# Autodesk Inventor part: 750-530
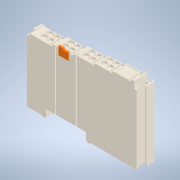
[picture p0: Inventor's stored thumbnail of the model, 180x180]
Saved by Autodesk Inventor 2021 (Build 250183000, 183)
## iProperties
Created: 2026-07
Part Number: 750-530
Material: Generic
Catalog Web Link: www.3dfindit.com
Description: 750-530-8-channel digital output module 24 VDC 0.5 A high-side switching short-circuit protected
Vendor: WAGO
Document SubType Name: Modeling
Designer: psAdmin
Manufacturer: WAGO
Mass: 49.754 g
Surface Area: 192.522 cm^2
Volume: 65.9871 cm^3
Density: 1 g/cm^3
Appearance: PSOLRGB-222-214-201
Category: PARTsolutions
Company: WAGO
Title: 750-530
Author: Cadenas PARTsolutions
Comments: 8-channel digital output module 24 VDC 0.5 A high-side switching short-circuit protected
PSOL_IDENT_0: {$CADENAS_DATA/23d-libs/wago/pg15/serie750/0750-0530_0999-0962.prj},157 {VTYP=3D},{NB=750-530},{LINA=
PSOL_IDENT_1: 750-530},{NN=750-530},{DATE=29.04.2026 11:59:10},{GEOMDATE=22.04.2022 08:42:40},{VERSION=},{LINEID=1
PSOL_IDENT_2: 710},{WBVAR=},{WBNUMERIC=}  {NB=750-530},{LINA=750-530},{KT=DUMMY},{BESTNR=750-530},{INFODE=Info DE}
PSOL_IDENT_3: ,{INFOEN=Info EN},{QUERSCHNITT1=0.08 - 2.5},{QUERSCHNITT2=28 - 14},{ABISOLIERLAENGE=8 - 9},{HOEHE=64
PSOL_IDENT_4: .00},{BREITE=12.00},{TIEFE=100.00},{FARBE=lichtgrau},{GEWICHT=49.754},{BEMERKUNGEN=24V DC 0,5 A},{RG
PSOL_IDENT_5: B=0.87,0.84,0.79,0},{ECLASS71=27-24-26-04},{LINKDE=http://www.wago.com/de/p/750-530},{LINKEN=http://
PSOL_IDENT_6: www.wago.com/global/p/750-530},{FILENAME=750-530}
NB: 750-530
NN: 750-530
NT: 8-channel digital output module 24 VDC 0.5 A high-side switching short-circuit protected
NBSYN: $BESTNR.
LINA: 750-530
CATALOG: WAGO
OFFICIAL_STANDARD_NUMBERS: NO
BESTNR: 750-530
INFODE: Info DE
INFOEN: Info EN
QUERSCHNITT1: 0.08 - 2.5
QUERSCHNITT2: 28 - 14
ABISOLIERLAENGE: 8 - 9
HOEHE: 64
BREITE: 12
TIEFE: 100
FARBE: lichtgrau
GEWICHT: 49.754
BEMERKUNGEN: 24V DC 0,5 A
ECLASS71: 27-24-26-04
SUPPLIER: WAGO
ARTICLENO: 750-530
BOMINFO: 750-530
CREATOR: CADENAS GmbH
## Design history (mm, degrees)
sketch "Skizze_1"
  geometry: L1 (-32.4, 49.707)-(-32.4, -6.4); L2 (-32.4, -6.4)-(-21.968, -6.4); L3 (-21.968, -6.4)-(-20.7, -7.132); L4 (-17.7, -5.4)-(-17.7, 0); L5 (-17.7, 0)-(17.7, 0); L6 (17.7, 0)-(17.7, -5.4); L7 (20.7, -7.132)-(21.968, -6.4); L8 (21.968, -6.4)-(60, -6.4); L9 (60, -6.4)-(60, 59.4); L10 (59, 60.4)-(58.817, 60.4); L11 (58.529, 60.278)-(58.453, 60.199); L12 (59.036, 58.958)-(58.958, 58.766); L13 (58.958, 58.766)-(54.895, 57.042); L14 (54.895, 57.042)-(54.703, 57.119); L15 (54.215, 58.4)-(41.912, 58.4); L16 (41.912, 58.4)-(41.803, 58.354); L17 (41.803, 58.354)-(41.653, 58.199); L18 (42.236, 56.958)-(42.158, 56.766); L19 (42.158, 56.766)-(38.095, 55.042); L20 (38.095, 55.042)-(37.903, 55.119); L21 (37.415, 56.4)-(25.912, 56.4); L22 (25.912, 56.4)-(25.803, 56.354); L23 (25.803, 56.354)-(25.653, 56.199); L24 (26.236, 54.958)-(26.158, 54.766); L25 (26.158, 54.766)-(22.095, 53.042); L26 (22.095, 53.042)-(21.903, 53.119); L27 (21.415, 54.4)-(7.512, 54.4); L28 (7.512, 54.4)-(7.403, 54.354); L29 (7.403, 54.354)-(7.253, 54.199); L30 (7.836, 52.958)-(7.758, 52.766); L31 (7.758, 52.766)-(3.695, 51.042); L32 (3.695, 51.042)-(3.503, 51.119); L33 (3.015, 52.4)-(-10.888, 52.4); L34 (-10.888, 52.4)-(-10.997, 52.354); L35 (-10.997, 52.354)-(-11.147, 52.199); L36 (-10.564, 50.958)-(-10.642, 50.766); L37 (-10.642, 50.766)-(-14.705, 49.042); L38 (-14.705, 49.042)-(-14.897, 49.119); L39 (-15.385, 50.4)-(-32, 50.4); L40 (-32, 50.4)-(-32.4, 49.707); A1 r 2 centre (-19.7, -5.4) between (-20.7, -7.132) and (-17.7, -5.4); A2 r 2 centre (19.7, -5.4) between (17.7, -5.4) and (20.7, -7.132); A3 r 1 centre (59, 59.4) between (60, 59.4) and (59, 60.4); A4 r 0.4 centre (58.817, 60) between (58.817, 60.4) and (58.529, 60.278); A5 r 0.332 centre (58.692, 59.969) between (58.453, 60.199) and (58.644, 59.641); A6 r 0.5 centre (58.572, 59.146) between (59.036, 58.958) and (58.644, 59.641); A7 r 0.5 centre (54.89, 57.583) between (54.484, 57.875) and (54.703, 57.119); A8 r 0.332 centre (54.215, 58.068) between (54.484, 57.875) and (54.215, 58.4); A9 r 0.332 centre (41.892, 57.969) between (41.653, 58.199) and (41.844, 57.641); A10 r 0.5 centre (41.772, 57.146) between (42.236, 56.958) and (41.844, 57.641); A11 r 0.5 centre (38.09, 55.583) between (37.684, 55.875) and (37.903, 55.119); A12 r 0.332 centre (37.415, 56.068) between (37.684, 55.875) and (37.415, 56.4); A13 r 0.332 centre (25.892, 55.969) between (25.653, 56.199) and (25.844, 55.641); A14 r 0.5 centre (25.772, 55.146) between (26.236, 54.958) and (25.844, 55.641); A15 r 0.5 centre (22.09, 53.583) between (21.684, 53.875) and (21.903, 53.119); A16 r 0.332 centre (21.415, 54.068) between (21.684, 53.875) and (21.415, 54.4); A17 r 0.331 centre (7.492, 53.969) between (7.253, 54.199) and (7.444, 53.641); A18 r 0.5 centre (7.372, 53.146) between (7.836, 52.958) and (7.444, 53.641); A19 r 0.5 centre (3.69, 51.583) between (3.284, 51.875) and (3.503, 51.119); A20 r 0.332 centre (3.015, 52.068) between (3.284, 51.875) and (3.015, 52.4); A21 r 0.332 centre (-10.908, 51.969) between (-11.147, 52.199) and (-10.956, 51.641); A22 r 0.5 centre (-11.028, 51.146) between (-10.564, 50.958) and (-10.956, 51.641); A23 r 0.5 centre (-14.71, 49.583) between (-15.116, 49.875) and (-14.897, 49.119); A24 r 0.332 centre (-15.385, 50.068) between (-15.116, 49.875) and (-15.385, 50.4)
  constraints: 80 end point, 48 point on circle, 24 centre point
extrude "Extrusion1" join sketch "Skizze_1" distance "d0" = 12; taper "d1" = 0 deg
sketch "Skizze_10"
  geometry: L1 (37.2, 56.4)-(37.981, 54.559); L2 (37.981, 54.559)-(42.693, 56.559); L3 (42.693, 56.559)-(41.912, 58.4); L4 (41.912, 58.4)-(41.342, 58.158); L5 (40.812, 56.847)-(38.971, 56.066); L6 (37.66, 56.595)-(37.2, 56.4); A1 r 1 centre (41.733, 57.238) between (41.342, 58.158) and (40.812, 56.847); A2 r 1 centre (38.051, 55.675) between (38.971, 56.066) and (37.66, 56.595)
  constraints: 12 end point, 4 point on circle, 2 centre point
extrude "Extrusion2" join sketch "Skizze_10" distance "d2" = 0.5; taper "d3" = 0 deg
sketch "Skizze_11"
  geometry: L1 (21.2, 54.4)-(21.981, 52.559); L2 (21.981, 52.559)-(26.693, 54.559); L3 (26.693, 54.559)-(25.912, 56.4); L4 (25.912, 56.4)-(25.342, 56.158); L5 (24.812, 54.847)-(22.971, 54.066); L6 (21.66, 54.595)-(21.2, 54.4); A1 r 1 centre (25.733, 55.238) between (25.342, 56.158) and (24.812, 54.847); A2 r 1 centre (22.051, 53.675) between (22.971, 54.066) and (21.66, 54.595)
  constraints: 12 end point, 4 point on circle, 2 centre point
extrude "Extrusion3" join sketch "Skizze_11" distance "d4" = 0.5; taper "d5" = 0 deg
sketch "Skizze_12"
  geometry: L1 (2.8, 52.4)-(3.581, 50.559); L2 (3.581, 50.559)-(8.293, 52.559); L3 (8.293, 52.559)-(7.512, 54.4); L4 (7.512, 54.4)-(6.942, 54.158); L5 (6.412, 52.847)-(4.571, 52.066); L6 (3.26, 52.595)-(2.8, 52.4); A1 r 1 centre (7.333, 53.238) between (6.942, 54.158) and (6.412, 52.847); A2 r 1 centre (3.651, 51.675) between (4.571, 52.066) and (3.26, 52.595)
  constraints: 12 end point, 4 point on circle, 2 centre point
extrude "Extrusion4" join sketch "Skizze_12" distance "d6" = 0.5; taper "d7" = 0 deg
sketch "Skizze_13"
  geometry: L1 (-15.6, 50.4)-(-14.819, 48.559); L2 (-14.819, 48.559)-(-10.107, 50.559); L3 (-10.107, 50.559)-(-10.888, 52.4); L4 (-10.888, 52.4)-(-11.458, 52.158); L5 (-11.988, 50.847)-(-13.829, 50.066); L6 (-15.14, 50.595)-(-15.6, 50.4); A1 r 1 centre (-11.067, 51.238) between (-11.458, 52.158) and (-11.988, 50.847); A2 r 1 centre (-14.749, 49.675) between (-13.829, 50.066) and (-15.14, 50.595)
  constraints: 12 end point, 4 point on circle, 2 centre point
extrude "Extrusion5" join sketch "Skizze_13" distance "d8" = 0.5; taper "d9" = 0 deg
sketch "Skizze_60"
  geometry: L1 (54, 58.4)-(54.781, 56.559); L2 (54.781, 56.559)-(59.493, 58.559); L3 (59.493, 58.559)-(58.712, 60.4); L4 (58.712, 60.4)-(58.142, 60.158); L5 (57.612, 58.847)-(55.771, 58.066); L6 (54.46, 58.595)-(54, 58.4); A1 r 1 centre (58.533, 59.238) between (58.142, 60.158) and (57.612, 58.847); A2 r 1 centre (54.851, 57.675) between (55.771, 58.066) and (54.46, 58.595)
  constraints: 12 end point, 4 point on circle, 2 centre point
extrude "Extrusion6" join sketch "Skizze_60" distance "d10" = 0.5; taper "d11" = 0 deg
sketch "Skizze_14"
  geometry: L1 (37.2, 56.4)-(37.981, 54.559); L2 (37.981, 54.559)-(42.693, 56.559); L3 (42.693, 56.559)-(41.912, 58.4); L4 (41.912, 58.4)-(41.342, 58.158); L5 (40.812, 56.847)-(38.971, 56.066); L6 (37.66, 56.595)-(37.2, 56.4); A1 r 1 centre (41.733, 57.238) between (41.342, 58.158) and (40.812, 56.847); A2 r 1 centre (38.051, 55.675) between (38.971, 56.066) and (37.66, 56.595)
  constraints: 12 end point, 4 point on circle, 2 centre point
extrude "Extrusion7" join sketch "Skizze_14" distance "d12" = 0.5; taper "d13" = 0 deg
sketch "Skizze_15"
  geometry: L1 (21.2, 54.4)-(21.981, 52.559); L2 (21.981, 52.559)-(26.693, 54.559); L3 (26.693, 54.559)-(25.912, 56.4); L4 (25.912, 56.4)-(25.342, 56.158); L5 (24.812, 54.847)-(22.971, 54.066); L6 (21.66, 54.595)-(21.2, 54.4); A1 r 1 centre (25.733, 55.238) between (25.342, 56.158) and (24.812, 54.847); A2 r 1 centre (22.051, 53.675) between (22.971, 54.066) and (21.66, 54.595)
  constraints: 12 end point, 4 point on circle, 2 centre point
extrude "Extrusion8" join sketch "Skizze_15" distance "d14" = 0.5; taper "d15" = 0 deg
sketch "Skizze_16"
  geometry: L1 (2.8, 52.4)-(3.581, 50.559); L2 (3.581, 50.559)-(8.293, 52.559); L3 (8.293, 52.559)-(7.512, 54.4); L4 (7.512, 54.4)-(6.942, 54.158); L5 (6.412, 52.847)-(4.571, 52.066); L6 (3.26, 52.595)-(2.8, 52.4); A1 r 1 centre (7.333, 53.238) between (6.942, 54.158) and (6.412, 52.847); A2 r 1 centre (3.651, 51.675) between (4.571, 52.066) and (3.26, 52.595)
  constraints: 12 end point, 4 point on circle, 2 centre point
extrude "Extrusion9" join sketch "Skizze_16" distance "d16" = 0.5; taper "d17" = 0 deg
sketch "Skizze_17"
  geometry: L1 (-15.6, 50.4)-(-14.819, 48.559); L2 (-14.819, 48.559)-(-10.107, 50.559); L3 (-10.107, 50.559)-(-10.888, 52.4); L4 (-10.888, 52.4)-(-11.458, 52.158); L5 (-11.988, 50.847)-(-13.829, 50.066); L6 (-15.14, 50.595)-(-15.6, 50.4); A1 r 1 centre (-11.067, 51.238) between (-11.458, 52.158) and (-11.988, 50.847); A2 r 1 centre (-14.749, 49.675) between (-13.829, 50.066) and (-15.14, 50.595)
  constraints: 12 end point, 4 point on circle, 2 centre point
extrude "Extrusion10" join sketch "Skizze_17" distance "d18" = 0.5; taper "d19" = 0 deg
sketch "Skizze_61"
  geometry: L1 (54, 58.4)-(54.781, 56.559); L2 (54.781, 56.559)-(59.493, 58.559); L3 (59.493, 58.559)-(58.712, 60.4); L4 (58.712, 60.4)-(58.142, 60.158); L5 (57.612, 58.847)-(55.771, 58.066); L6 (54.46, 58.595)-(54, 58.4); A1 r 1 centre (58.533, 59.238) between (58.142, 60.158) and (57.612, 58.847); A2 r 1 centre (54.851, 57.675) between (55.771, 58.066) and (54.46, 58.595)
  constraints: 12 end point, 4 point on circle, 2 centre point
extrude "Extrusion11" join sketch "Skizze_61" distance "d20" = 0.5; taper "d21" = 0 deg
sketch "Skizze_46"
  geometry: L1 (-7.3, 46.4)-(2.5, 46.4); L2 (2.5, 46.4)-(2.5, 52.4); L3 (2.5, 52.4)-(-7.3, 52.4); L4 (-7.3, 52.4)-(-7.3, 46.4)
  constraints: 8 end point
extrude "Extrusion12" cut sketch "Skizze_46" distance "d22" = 1.9; taper "d23" = 0 deg
sketch "Skizze_47"
  geometry: L1 (-7, 53.4)-(-7, 46.6); L2 (-6.8, 46.4)-(2, 46.4); L3 (2.2, 46.6)-(2.2, 52.2); L4 (2, 52.4)-(-3.3, 52.4); L5 (-3.331, 52.998)-(-2.325, 53.101); L6 (-2.35, 53.6)-(-6.8, 53.6); A1 r 0.2 centre (-6.8, 46.6) between (-7, 46.6) and (-6.8, 46.4); A2 r 0.2 centre (2, 46.6) between (2, 46.4) and (2.2, 46.6); A3 r 0.2 centre (2, 52.2) between (2.2, 52.2) and (2, 52.4); A4 r 0.3 centre (-3.3, 52.7) between (-3.331, 52.998) and (-3.3, 52.4); A5 r 0.25 centre (-2.35, 53.35) between (-2.325, 53.101) and (-2.35, 53.6); A6 r 0.2 centre (-6.8, 53.4) between (-6.8, 53.6) and (-7, 53.4)
  constraints: 12 end point, 12 point on circle, 6 centre point
extrude "Extrusion13" join sketch "Skizze_47" stored distance "d24" = 1.6; taper "d25" = 0 deg
sketch "Skizze_2"
  geometry: L1 (60, 0)-(60, -1.7); L2 (60.5, -1.2)-(61.9, -1.2); L3 (62.4, -1.7)-(62.4, -4.3); L4 (63.8, -4.3)-(63.8, 1.8); L5 (62.8, 2.8)-(61.3, 2.8); L6 (60.8, 2.3)-(60.8, 1.9); L7 (61, 1.7)-(62.2, 1.7); L8 (62.4, 1.5)-(62.4, 0.2); L9 (62.2, 0)-(60, 0); A1 r 0.5 centre (60.5, -1.7) between (60.5, -1.2) and (60, -1.7); A2 r 0.5 centre (61.9, -1.7) between (62.4, -1.7) and (61.9, -1.2); A3 r 0.7 centre (63.1, -4.3) between (62.4, -4.3) and (63.8, -4.3); A4 r 1 centre (62.8, 1.8) between (63.8, 1.8) and (62.8, 2.8); A5 r 0.5 centre (61.3, 2.3) between (61.3, 2.8) and (60.8, 2.3); A6 r 0.2 centre (61, 1.9) between (60.8, 1.9) and (61, 1.7); A7 r 0.2 centre (62.2, 1.5) between (62.4, 1.5) and (62.2, 1.7); A8 r 0.2 centre (62.2, 0.2) between (62.2, 0) and (62.4, 0.2)
  constraints: 18 end point, 16 point on circle, 8 centre point
extrude "Extrusion14" join sketch "Skizze_2" distance "d26" = 60.8; taper "d27" = 0 deg
sketch "Skizze_3"
  geometry: L1 (-34.8, -4.3)-(-34.8, -1.7); L2 (-34.3, -1.2)-(-32.9, -1.2); L3 (-32.4, -1.7)-(-32.4, 0); L4 (-32.4, 0)-(-34.6, 0); L5 (-34.8, 0.2)-(-34.8, 1.5); L6 (-34.6, 1.7)-(-33.4, 1.7); L7 (-33.2, 1.9)-(-33.2, 2.3); L8 (-33.7, 2.8)-(-35.2, 2.8); L9 (-36.2, 1.8)-(-36.2, -4.3); A1 r 0.7 centre (-35.5, -4.3) between (-36.2, -4.3) and (-34.8, -4.3); A2 r 0.5 centre (-34.3, -1.7) between (-34.3, -1.2) and (-34.8, -1.7); A3 r 0.5 centre (-32.9, -1.7) between (-32.4, -1.7) and (-32.9, -1.2); A4 r 0.2 centre (-34.6, 0.2) between (-34.8, 0.2) and (-34.6, 0); A5 r 0.2 centre (-34.6, 1.5) between (-34.6, 1.7) and (-34.8, 1.5); A6 r 0.2 centre (-33.4, 1.9) between (-33.4, 1.7) and (-33.2, 1.9); A7 r 0.5 centre (-33.7, 2.3) between (-33.2, 2.3) and (-33.7, 2.8); A8 r 1 centre (-35.2, 1.8) between (-35.2, 2.8) and (-36.2, 1.8)
  constraints: 18 end point, 16 point on circle, 8 centre point
extrude "Extrusion15" join sketch "Skizze_3" distance "d28" = 54.8; taper "d29" = 0 deg
sketch "Skizze_9"
  geometry: L1 (-34.6, -10.6)-(-34.6, -11.8); L2 (-34.4, -12)-(-32.4, -12); L3 (-32.4, -12)-(-32.4, -7); L4 (-32.4, -7)-(-33, -7); L5 (-33, -7)-(-33, -10.4); L6 (-33, -10.4)-(-34.4, -10.4); A1 r 0.2 centre (-34.4, -11.8) between (-34.6, -11.8) and (-34.4, -12); A2 r 0.2 centre (-34.4, -10.6) between (-34.4, -10.4) and (-34.6, -10.6)
  constraints: 12 end point, 4 point on circle, 2 centre point
extrude "Extrusion16" join sketch "Skizze_9" distance "d30" = 54.8; taper "d31" = 0 deg
sketch "Skizze_8"
  geometry: L1 (60, -7)-(60, -12); L2 (60, -12)-(62, -12); L3 (62.2, -11.8)-(62.2, -10.6); L4 (62, -10.4)-(60.6, -10.4); L5 (60.6, -10.4)-(60.6, -7); L6 (60.6, -7)-(60, -7); A1 r 0.2 centre (62, -11.8) between (62, -12) and (62.2, -11.8); A2 r 0.2 centre (62, -10.6) between (62.2, -10.6) and (62, -10.4)
  constraints: 12 end point, 4 point on circle, 2 centre point
extrude "Extrusion17" join sketch "Skizze_8" distance "d32" = 60.8; taper "d33" = 0 deg
sketch "Sketch18"
  geometry: 1 further point
hole "Hole1" sketch "Sketch18" at (3.188, 9.5) diameter "d34" = 4.2; stored, may be unused: countersink angle "d38" = 90 deg, drill point angle "d40" = 0 deg; dims "d35" = 6, "d36" = 5.4, "d37" = 2, "d39" = 2
pattern_linear "Rectangular Pattern1" dims "d43" = 5, "d46" = 0
sketch "Skizze_24"
  geometry: L1 (-2.5, 54.4)-(-2.5, 56.4); L2 (-2.5, 56.4)-(-1.2, 56.4); L3 (-1.2, 56.4)-(-1.4, 55.8); L4 (-1.4, 55.8)-(-1.4, 54.4); L5 (-1.4, 54.4)-(-2.5, 54.4); L6 (-2.5, 54.4)-(-2.5, 56.4)
  constraints: 12 end point
revolve "Revolution1" sketch "Skizze_24" stored, may be unused: angle "d47" = 360 deg
pattern_linear "Rectangular Pattern2" dims "d50" = 5, "d53" = 0
sketch "Skizze_26"
  geometry: L1 (-4.5, 54.4)-(-0.8, 54.4); L2 (-0.8, 54.4)-(-0.8, 56.4); L3 (-0.8, 56.4)-(-4.5, 56.4); L4 (-4.5, 56.4)-(-4.5, 54.4)
  constraints: 8 end point
extrude "Extrusion18" cut sketch "Skizze_26" distance "d54" = 3.8; taper "d55" = 0 deg
pattern_linear "Rectangular Pattern3" dims "d58" = 5, "d61" = 0
sketch "Sketch21"
  geometry: 1 further point
hole "Hole2" sketch "Sketch21" at (5.588, 9.5) diameter "d62" = 4.2; stored, may be unused: countersink angle "d66" = 90 deg, drill point angle "d68" = 0 deg; dims "d63" = 6, "d64" = 5.4, "d65" = 2, "d67" = 2
pattern_linear "Rectangular Pattern4" dims "d71" = 5, "d74" = 0
sketch "Skizze_30"
  geometry: L1 (-2.5, 52.4)-(-2.5, 54.4); L2 (-2.5, 54.4)-(-1.2, 54.4); L3 (-1.2, 54.4)-(-1.4, 53.8); L4 (-1.4, 53.8)-(-1.4, 52.4); L5 (-1.4, 52.4)-(-2.5, 52.4); L6 (-2.5, 52.4)-(-2.5, 54.4)
  constraints: 12 end point
revolve "Revolution2" sketch "Skizze_30" stored, may be unused: angle "d75" = 360 deg
pattern_linear "Rectangular Pattern5" dims "d78" = 5, "d81" = 0
sketch "Skizze_32"
  geometry: L1 (-4.5, 52.4)-(-0.8, 52.4); L2 (-0.8, 52.4)-(-0.8, 54.4); L3 (-0.8, 54.4)-(-4.5, 54.4); L4 (-4.5, 54.4)-(-4.5, 52.4)
  constraints: 8 end point
extrude "Extrusion19" cut sketch "Skizze_32" distance "d82" = 3.8; taper "d83" = 0 deg
pattern_linear "Rectangular Pattern6" dims "d86" = 5, "d89" = 0
sketch "Sketch24"
  geometry: 1 further point
hole "Hole3" sketch "Sketch24" at (5.588, 9.5) diameter "d90" = 4.2; stored, may be unused: countersink angle "d94" = 90 deg, drill point angle "d96" = 0 deg; dims "d91" = 6, "d92" = 5.4, "d93" = 2, "d95" = 2
pattern_linear "Rectangular Pattern7" dims "d99" = 5, "d102" = 0
sketch "Skizze_36"
  geometry: L1 (-2.5, 50.4)-(-2.5, 52.4); L2 (-2.5, 52.4)-(-1.2, 52.4); L3 (-1.2, 52.4)-(-1.4, 51.8); L4 (-1.4, 51.8)-(-1.4, 50.4); L5 (-1.4, 50.4)-(-2.5, 50.4); L6 (-2.5, 50.4)-(-2.5, 52.4)
  constraints: 12 end point
revolve "Revolution3" sketch "Skizze_36" stored, may be unused: angle "d103" = 360 deg
pattern_linear "Rectangular Pattern8" dims "d106" = 5, "d109" = 0
sketch "Skizze_38"
  geometry: L1 (-4.5, 50.4)-(-0.8, 50.4); L2 (-0.8, 50.4)-(-0.8, 52.4); L3 (-0.8, 52.4)-(-4.5, 52.4); L4 (-4.5, 52.4)-(-4.5, 50.4)
  constraints: 8 end point
extrude "Extrusion20" cut sketch "Skizze_38" distance "d110" = 3.8; taper "d111" = 0 deg
pattern_linear "Rectangular Pattern9" dims "d114" = 5, "d117" = 0
sketch "Sketch27"
  geometry: 1 further point
hole "Hole4" sketch "Sketch27" at (8.3, 9.5) diameter "d118" = 4.2; stored, may be unused: countersink angle "d122" = 90 deg, drill point angle "d124" = 0 deg; dims "d119" = 6, "d120" = 5.4, "d121" = 2, "d123" = 2
pattern_linear "Rectangular Pattern10" dims "d127" = 5, "d130" = 0
sketch "Skizze_42"
  geometry: L1 (-2.5, 48.4)-(-2.5, 50.4); L2 (-2.5, 50.4)-(-1.2, 50.4); L3 (-1.2, 50.4)-(-1.4, 49.8); L4 (-1.4, 49.8)-(-1.4, 48.4); L5 (-1.4, 48.4)-(-2.5, 48.4); L6 (-2.5, 48.4)-(-2.5, 50.4)
  constraints: 12 end point
revolve "Revolution4" sketch "Skizze_42" stored, may be unused: angle "d131" = 360 deg
pattern_linear "Rectangular Pattern11" dims "d134" = 5, "d137" = 0
sketch "Skizze_44"
  geometry: L1 (-4.5, 48.4)-(-0.8, 48.4); L2 (-0.8, 48.4)-(-0.8, 50.4); L3 (-0.8, 50.4)-(-4.5, 50.4); L4 (-4.5, 50.4)-(-4.5, 48.4)
  constraints: 8 end point
extrude "Extrusion21" cut sketch "Skizze_44" distance "d138" = 3.8; taper "d139" = 0 deg
pattern_linear "Rectangular Pattern12" dims "d142" = 5, "d145" = 0
sketch "Skizze_4"
  geometry: L1 (42.9, 57.9)-(53.7, 57.9); L2 (53.7, 57.9)-(53.7, 58.4); L3 (53.7, 58.4)-(42.9, 58.4); L4 (42.9, 58.4)-(42.9, 57.9)
  constraints: 8 end point
extrude "Extrusion22" cut sketch "Skizze_4" distance "d146" = 9.05; taper "d147" = 0 deg
sketch "Sketch_1"
  geometry: L1 (9.7, 13)-(-9.7, 13); L2 (-9.7, 13)-(-9.7, 9.4); L3 (-9.7, 9.4)-(-8.7, 9.4); L4 (-8.7, 9.4)-(-8.7, 12); L5 (-8.7, 12)-(8.7, 12); L6 (8.7, 12)-(8.7, 9.4); L7 (8.7, 9.4)-(9.7, 9.4); L8 (9.7, 9.4)-(9.7, 13)
  constraints: 16 end point
extrude "Extrusion23" cut sketch "Sketch_1" distance "d148" = 55; taper "d149" = 0 deg
sketch "Sketch_2"
  geometry: L1 (8.95, 44.9)-(8.95, 41.3); L2 (8.95, 41.3)-(9.35, 41.3); L3 (9.35, 41.3)-(9.35, 44.9); L4 (9.35, 44.9)-(8.95, 44.9)
  constraints: 8 end point
extrude "Extrusion24" join sketch "Sketch_2" distance "d150" = 2.4; taper "d151" = 0 deg
sketch "Sketch_3"
  geometry: L1 (-9.45, 42.9)-(-9.45, 39.3); L2 (-9.45, 39.3)-(-9.05, 39.3); L3 (-9.05, 39.3)-(-9.05, 42.9); L4 (-9.05, 42.9)-(-9.45, 42.9)
  constraints: 8 end point
extrude "Extrusion25" join sketch "Sketch_3" distance "d152" = 2.4; taper "d153" = 0 deg
node "1_10_XY"
node "1_10_YZ"
node "1_10_ZX"
node "1_10_X"
node "1_10_Y"
node "1_10_Z"
node "1_10_Center"
node "1_11_XY"
node "1_11_YZ"
node "1_11_ZX"
node "1_11_X"
node "1_11_Y"
node "1_11_Z"
node "1_11_Center"
node "1_12_XY"
node "1_12_YZ"
node "1_12_ZX"
node "1_12_X"
node "1_12_Y"
node "1_12_Z"
node "1_12_Center"
node "1_13_XY"
node "1_13_YZ"
node "1_13_ZX"
node "1_13_X"
node "1_13_Y"
node "1_13_Z"
node "1_13_Center"
node "1_14_XY"
node "1_14_YZ"
node "1_14_ZX"
node "1_14_X"
node "1_14_Y"
node "1_14_Z"
node "1_14_Center"
node "1_15_XY"
node "1_15_YZ"
node "1_15_ZX"
node "1_15_X"
node "1_15_Y"
node "1_15_Z"
node "1_15_Center"
node "1_16_XY"
node "1_16_YZ"
node "1_16_ZX"
node "1_16_X"
node "1_16_Y"
node "1_16_Z"
node "1_16_Center"
node "1_17_XY"
node "1_17_YZ"
node "1_17_ZX"
node "1_17_X"
node "1_17_Y"
node "1_17_Z"
node "1_17_Center"
node "1_18_XY"
node "1_18_YZ"
node "1_18_ZX"
node "1_18_X"
node "1_18_Y"
node "1_18_Z"
node "1_18_Center"
node "1_19_XY"
node "1_19_YZ"
node "1_19_ZX"
node "1_19_X"
node "1_19_Y"
node "1_19_Z"
node "1_19_Center"
node "1_2_XY"
node "1_2_YZ"
node "1_2_ZX"
node "1_2_X"
node "1_2_Y"
node "1_2_Z"
node "1_2_Center"
node "1_20_XY"
node "1_20_YZ"
node "1_20_ZX"
node "1_20_X"
node "1_20_Y"
node "1_20_Z"
node "1_20_Center"
node "1_21_XY"
node "1_21_YZ"
node "1_21_ZX"
node "1_21_X"
node "1_21_Y"
node "1_21_Z"
node "1_21_Center"
node "1_22_XY"
node "1_22_YZ"
node "1_22_ZX"
node "1_22_X"
node "1_22_Y"
node "1_22_Z"
node "1_22_Center"
node "1_23_XY"
node "1_23_YZ"
node "1_23_ZX"
node "1_23_X"
node "1_23_Y"
node "1_23_Z"
node "1_23_Center"
node "1_24_XY"
node "1_24_YZ"
node "1_24_ZX"
node "1_24_X"
node "1_24_Y"
node "1_24_Z"
node "1_24_Center"
node "1_25_XY"
node "1_25_YZ"
node "1_25_ZX"
node "1_25_X"
node "1_25_Y"
node "1_25_Z"
node "1_25_Center"
node "1_27_XY"
node "1_27_YZ"
node "1_27_ZX"
node "1_27_X"
node "1_27_Y"
node "1_27_Z"
node "1_27_Center"
node "1_28_XY"
node "1_28_YZ"
node "1_28_ZX"
node "1_28_X"
node "1_28_Y"
node "1_28_Z"
node "1_28_Center"
node "1_3_XY"
node "1_3_YZ"
node "1_3_ZX"
node "1_3_X"
node "1_3_Y"
node "1_3_Z"
node "1_3_Center"
node "1_4_XY"
node "1_4_YZ"
node "1_4_ZX"
node "1_4_X"
node "1_4_Y"
node "1_4_Z"
node "1_4_Center"
node "1_5_XY"
node "1_5_YZ"
node "1_5_ZX"
node "1_5_X"
node "1_5_Y"
node "1_5_Z"
node "1_5_Center"
node "1_6_XY"
node "1_6_YZ"
node "1_6_ZX"
node "1_6_X"
node "1_6_Y"
node "1_6_Z"
node "1_6_Center"
node "1_7_XY"
node "1_7_YZ"
node "1_7_ZX"
node "1_7_X"
node "1_7_Y"
node "1_7_Z"
node "1_7_Center"
node "1_8_XY"
node "1_8_YZ"
node "1_8_ZX"
node "1_8_X"
node "1_8_Y"
node "1_8_Z"
node "1_8_Center"
node "1_9_XY"
node "1_9_YZ"
node "1_9_ZX"
node "1_9_X"
node "1_9_Y"
node "1_9_Z"
node "1_9_Center"
body "Solid1"
other parameters: "d154" = 0, "d155" = 0, "d156" = 0, "d157" = 0, "d158" = 0, "d159" = 0, "d160" = 0, "d161" = 0, "d162" = 0, "d163" = 0, "d164" = 0, "d165" = 0, "d166" = 0, "d167" = 0, "d168" = 0, "d169" = 0, "d170" = 0, "d171" = 0, "d172" = 0, "d173" = 0, "d174" = 0, "d175" = 0, "d176" = 0, "d177" = 0, "d178" = 0, "d179" = 0
